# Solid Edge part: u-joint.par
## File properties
Title: Ypke
Author: Deepak Maini
Template: normal.par
Last saved by: CADCIM
Revision: 8
Application: Solid Edge
Density: 0.0000078 kg/mm^3
Accuracy: 0.01
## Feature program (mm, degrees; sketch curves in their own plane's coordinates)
sketch for "unnamed Protrusion 1" plane through (0, 0, 0) normal (0, -1, 0) x-axis (1, 0, 0)
  line (-44.45, -33.7976) -> (-44.45, 4.3024)
  arc centre (0, 4.3024) radius 44.45 from (-44.45, 4.3024) to (44.45, 4.3024) cw
  line (44.45, 4.3024) -> (44.45, -33.7976)
  line (44.45, -33.7976) -> (25.4, -33.7976)
  line (25.4, -33.7976) -> (25.4, 4.3024)
  arc centre (0, 4.3024) radius 25.4 from (-25.4, 4.3024) to (25.4, 4.3024) cw
  line (-25.4, -33.7976) -> (-25.4, 4.3024)
  line (-44.45, -33.7976) -> (-25.4, -33.7976)
extrude "unnamed Protrusion 1" add finite 50.8 along -normal
fillet "Round_3" radius 25.4
sketch for "Hole_1" plane through (44.45, 25.4, -14.7476) normal (1, 0, 0) x-axis (0, 1, 0)
  hole centre (0, 6.35) bore radius 9.525
hole "Hole_1" diameter 19.05 through
sketch for "ExtrudedProtrusion_2" plane through (46.6729, 25.4, 119.8724) normal (0, 0, 1) x-axis (-1, 0, 0)
  circle centre (46.6729, 0) radius 17.1196
extrude "ExtrudedProtrusion_2" add  Plane_Distance = 128.27 mm
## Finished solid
Body 1: solid body, 14 faces, 30 edges, 16 vertices.
  Faces by surface: cylinder 7, plane 7
  Edges by curve: line 16, circle 13, intersection 1
Bounding box of the edges (mm): 88.900 x 50.800 x 153.670, from (-44.45, 0, -33.7976) to (44.45, 50.8, 119.8724).
Cylindrical faces by radius (mm): R9.525 x2, R17.1196 x1, R25.4 x3, R44.45 x1
Planar faces by outward normal: +x 2, +y 1, +z 1, -x 2, -y 1
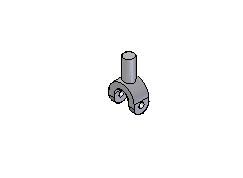
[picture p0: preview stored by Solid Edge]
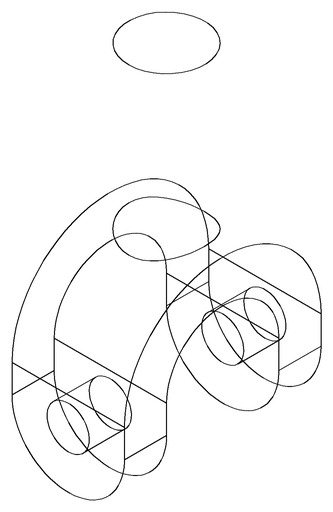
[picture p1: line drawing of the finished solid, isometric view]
